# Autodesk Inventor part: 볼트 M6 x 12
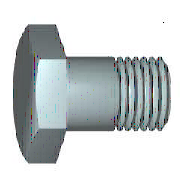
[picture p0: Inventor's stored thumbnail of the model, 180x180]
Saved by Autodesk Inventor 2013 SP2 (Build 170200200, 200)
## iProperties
IsCustomPart: 0
Created: 2012-02
Part Number: 볼트 M6 x 12
Material: 스테인리스강
Description: 6각 머리 나사. 제품 등급 C
Document SubType Name: Modeling
Standard: ISO 4018
Designer: mduedu
Standard Revision: Third edition 1999-08-15
Standards Organization: ISO
Language: ko-KR
Size Designation: M6 x 12
Categories: <MemberInstance><Categories><Category DisplayName="조임쇠" InternalName="e4da775c-781d-43d5-af7c-5136215cf5a6" Mnemonic="FSTN"><Category DisplayName="볼트" InternalN
Density: 8.08 g/cm^3
Author: mduedu
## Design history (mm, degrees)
node "WorkPlane1"
node "WorkPoint1"
node "MSC_A1"
node "MSC_PF1"
node "MSC_PT1"
body "Solid1"
node "스케치1"
sketch "스케치2"
  geometry: L1 (-5, 2.887)-(-5, -2.887); L2 (0, 5.773)-(-5, 2.887); L3 (5, 2.887)-(0, 5.773); L4 (5, -2.887)-(5, 2.887); L5 (0, -5.773)-(5, -2.887); L6 (-5, -2.887)-(0, -5.773); C1 r 5 at (0, 0); 1 further point
  constraints: 12 end point, 6 tangent, 2 parallel, 2 vertical, 1 centre point
  dimensions: "d1" = 10 diameter of C1 (= ParS); "d29" = 0 distance of point (0, 0) C1.centre; "d30" = 0 distance of C1.centre point (0, 0)
extrude "돌출1" new body sketch "스케치2" distance "d6" = 4 (= ParK); taper "d7" = 0 deg
revolve "회전1" stored, may be unused: angle "d14" = 360 deg
revolve "회전2" stored, may be unused: angle "d21" = 360 deg
chamfer "모따기1" distance "d22" = 0.5 (= 0.5 x PTC); stored, may be unused: second distance "d23" = 0.5 (= 0.5 x PTC), angle "d39" = 45 deg
fillet "모깎기1" dims "d24" = 0.25 (= r)
feature "스레드1" dims "d32" = 0, "b" = 10 (= NLG - 2 x PTC)
sketch "스케치3"
  geometry: L1 (5, 4)-(5.873, 4); L2 (5.873, 3.496)-(5, 4); L3 (5.873, 4)-(5.873, 3.496); L4 (0, -0.8)-(0, 4.8) reference; L5 (5.773, 0)-(5.773, 4) reference
  constraints: 6 end point, 1 horizontal, 1 vertical
  dimensions: "d25" = 0.1 distance between parallel lines of L5 L3; "d26" = 0 distance from line of L5.end L1; "d27" = 60 deg angle of L3 L2; "d28" = 5 distance from line of L4 L1.start (= 0.5 x ParS)
sketch "스케치4"
  geometry: L1 (0, -12)-(0, 0); L2 (-3, -12)-(0, -12); L3 (-3, 0)-(-3, -12); L4 (0, 0)-(-3, 0); L5 (0, -12)-(0, 0); L6 (-3.6, 0)-(0.6, 0) reference; L7 (0, -14.4)-(0, 2.4) reference
  constraints: 10 end point, 2 horizontal, 2 vertical
  dimensions: "d18" = 3 distance of L1.start L2.start (= 0.5 x NND); "d20" = 12 distance of L3.start L2.start (= NLG); "d33" = 0 distance between parallel lines of L7 L1; "d34" = 0 distance between parallel lines of L6 L4
other parameters: "NND" = 6 [user parameter; used in 2 equation terms], "NLG" = 12 [user parameter; used in 2 equation terms], "PTC" = 1 [user parameter; used in 3 equation terms], "ParK" = 4 [user parameter; used in 1 equation term], "ParS" = 10 [user parameter; used in 3 equation terms], "msp_es" = 5.77367 (= 0.577367 x ParS) [user parameter], "r" = 0.25 [user parameter; used in 1 equation term], "d2" = 15 (derived), "d4" = 17.32102 (derived), "d8" = 15 (derived), "d10" = 0 (derived), "d12" = 30 deg (derived), "d15" = 0 (derived), "d37" = 0, "d38" = 0, "d40" = 0, "d41" = 0, "d42" = 0, "THREADDIA" = 6 (= NND) [user parameter]
